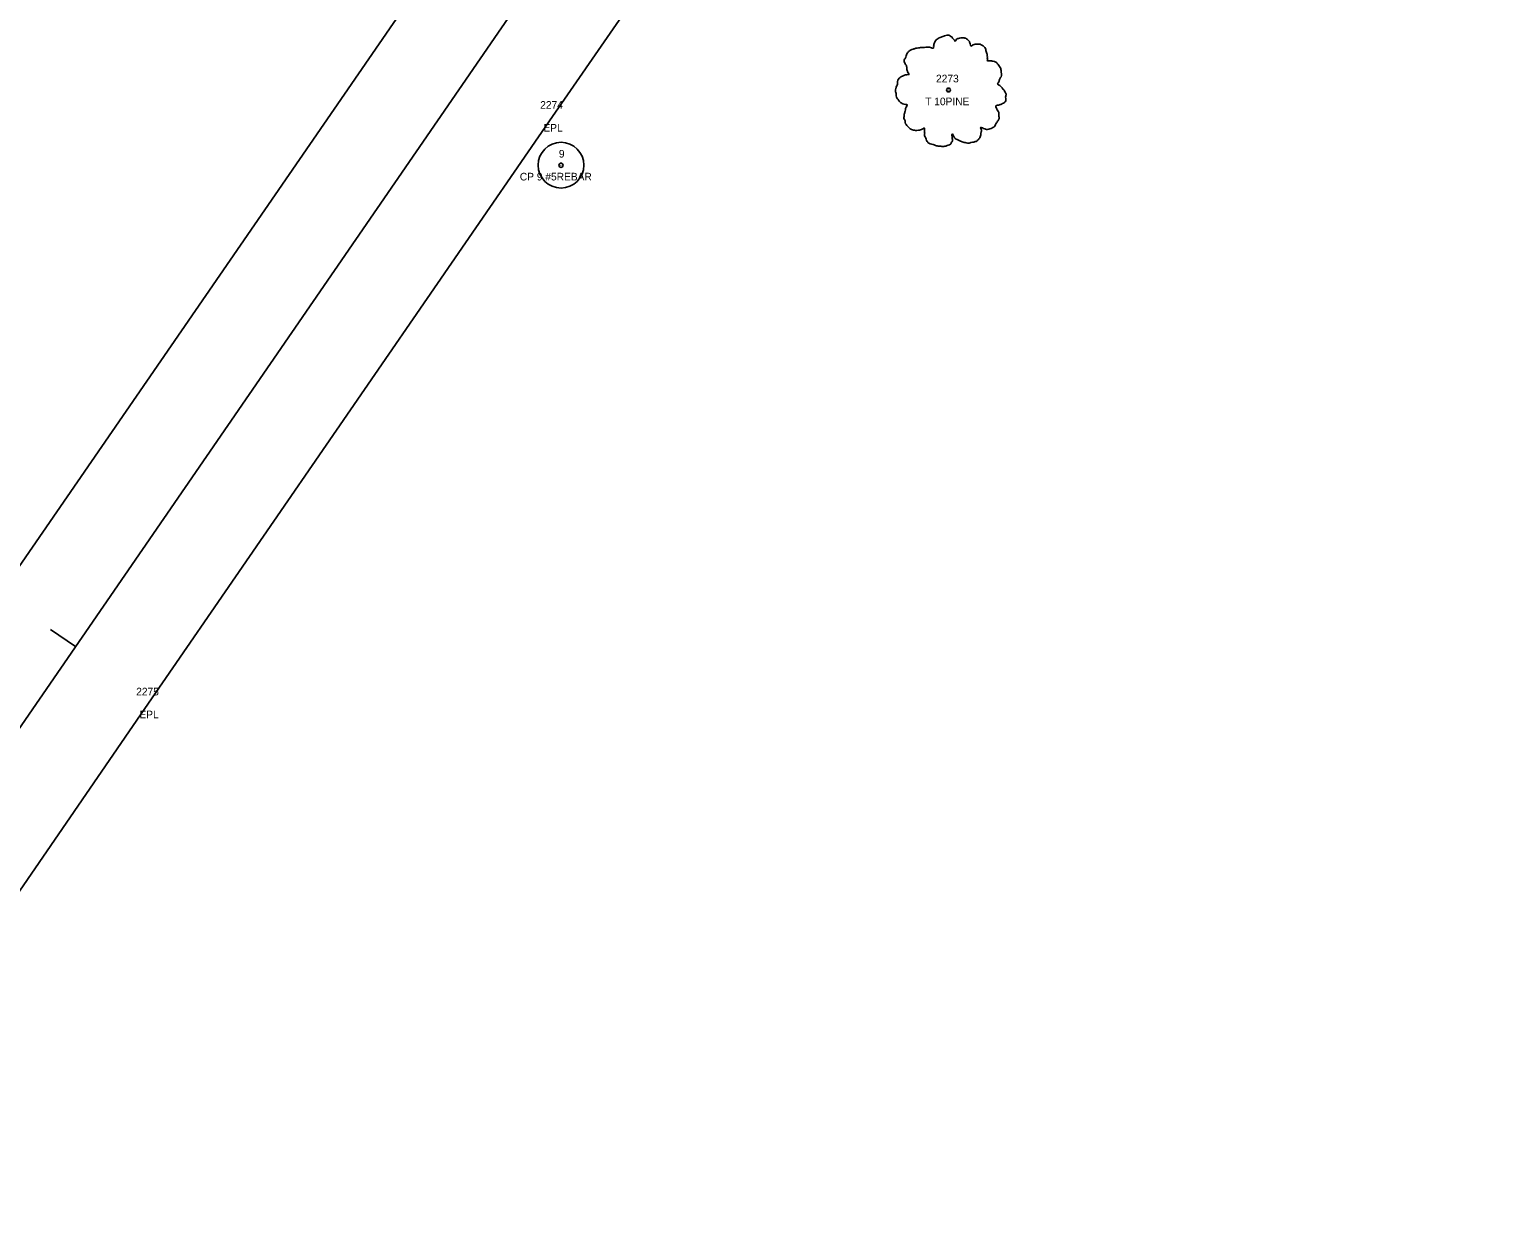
# Model space of a CAD drawing. Extents: x 2266664 to 2272542, y 716533 to 724777.
# Drawn here: x 2271769.3 to 2271962, y 723835.9 to 723993.3 of the extents above; entities that cross this region are included whole.
import ezdxf

# ---------------------------------------------------------------- set-up
doc = ezdxf.new("R2010")
doc.units = 0
for name, color, linetype in [('RD_EX_Road', 7, 'Continuous'), ('RD_EX_Road_txCode', 7, 'Continuous'), ('RD_EX_VEG', 7, 'Continuous'), ('RD_EX_VEG_txCode', 7, 'Continuous'), ('RD_HC_Cl', 7, 'Continuous'), ('RD_HC_Data', 7, 'Continuous'), ('RD_HC_Data_Tic', 7, 'Continuous'), ('RD_HC_txCode', 7, 'Continuous'), ('RD_SMD_Locator', 7, 'Continuous')]:
    doc.layers.add(name, color=color, linetype=linetype)

msp = doc.modelspace()

# ---------------------------------------------------------------- linework, layer by layer
at = {"layer": 'RD_EX_Road'}
for points in [[(2272350.52, 724770.05), (2272301.75, 724698.9), (2272265.2, 724646.02), (2272253.02, 724627.92), (2272200.51, 724550.87), (2272147.54, 724474.34), (2272126.28, 724443.66), (2272107.36, 724416.48), (2272092.2, 724393.69), (2272038.42, 724315.2), (2271991.52, 724247.47), (2271974.41, 724222.16), (2271928.73, 724155.87), (2271879.39, 724084.16), (2271852.9, 724045.63), (2271818.37, 723996.02), (2271765.12, 723918.77), (2271712.35, 723841.58), (2271659.05, 723763.61), (2271604.53, 723684.77), (2271550.65, 723606.61)], [(2272368.97, 724754.13), (2272346.57, 724721.92), (2272321.77, 724685.09), (2272273.25, 724614.42), (2272223.01, 724540.91), (2272206.83, 724517.64), (2272178.6, 724477.03), (2272166.48, 724459.37), (2272137.67, 724416.89), (2272108.53, 724374.93), (2272057.89, 724300.99), (2272036.24, 724269.85), (2272022.13, 724249.17), (2272003.16, 724221.27), (2271948.47, 724142.38), (2271900.7, 724072.99), (2271873.7, 724033.58), (2271837.94, 723981.87), (2271784.96, 723904.95), (2271732.12, 723828.06), (2271678.32, 723749.57), (2271627.92, 723676.62), (2271614.21, 723655.35), (2271570.62, 723593.07)]]:
    msp.add_lwpolyline(points, dxfattribs=at)
at = {"layer": 'RD_EX_VEG'}
for centre, radius in [((2271889.85, 723985.33), 0.25), ((2271889.83, 723985.32), 0.0001)]:
    msp.add_circle(centre, radius, dxfattribs=at)
for points in [[(2271889.98, 723992.5), (2271889.68, 723992.53), (2271889.35, 723992.43), (2271889.1, 723992.33), (2271888.88, 723992.25), (2271888.65, 723992.15), (2271888.35, 723991.98), (2271888.13, 723991.78), (2271888, 723991.53), (2271887.95, 723991.3), (2271887.9, 723991.03), (2271887.9, 723990.85), (2271887.78, 723990.83), (2271887.63, 723990.85), (2271887.38, 723990.93), (2271887.13, 723990.93), (2271886.88, 723990.93), (2271886.53, 723990.9), (2271886.18, 723990.9), (2271885.91, 723990.85), (2271885.58, 723990.8), (2271885.21, 723990.68), (2271884.86, 723990.55), (2271884.56, 723990.3), (2271884.31, 723989.83), (2271884.18, 723989.48), (2271884.03, 723989.23), (2271884.18, 723988.78), (2271884.36, 723988.43), (2271884.38, 723988.23), (2271884.46, 723987.8), (2271884.56, 723987.58), (2271884.68, 723987.38), (2271884.61, 723987.35), (2271884.23, 723987.3), (2271883.93, 723987.2), (2271883.51, 723986.98), (2271883.28, 723986.75), (2271883.18, 723986.43), (2271883.16, 723986.08), (2271883.06, 723985.88), (2271882.98, 723985.61), (2271882.96, 723985.53), (2271882.91, 723985.21), (2271883.01, 723984.76), (2271883.03, 723984.41), (2271883.16, 723984.18), (2271883.31, 723984.01), (2271883.48, 723983.76), (2271883.88, 723983.53), (2271884.21, 723983.43), (2271884.41, 723983.41), (2271884.23, 723982.91), (2271884.18, 723982.56), (2271884.06, 723982.16), (2271884.06, 723982.08), (2271884.01, 723981.61), (2271884.16, 723981.28), (2271884.23, 723980.91), (2271884.41, 723980.68), (2271884.68, 723980.38), (2271885.01, 723980.16), (2271885.51, 723980.03), (2271885.91, 723980.06), (2271886.48, 723980.23), (2271886.73, 723980.31), (2271886.7, 723980.13), (2271886.73, 723979.76), (2271886.73, 723979.33), (2271886.88, 723979.01), (2271886.98, 723978.73), (2271887.13, 723978.48), (2271887.45, 723978.26), (2271887.85, 723978.18), (2271888.28, 723978.03), (2271888.73, 723977.96), (2271889.23, 723977.93), (2271889.83, 723978.08), (2271890.1, 723978.21), (2271890.2, 723978.38), (2271890.4, 723978.76), (2271890.35, 723978.98), (2271890.38, 723979.58), (2271890.48, 723979.41), (2271890.65, 723979.06), (2271891.15, 723978.76), (2271891.55, 723978.58), (2271892.03, 723978.43), (2271892.33, 723978.36), (2271892.8, 723978.43), (2271893.18, 723978.51), (2271893.55, 723978.63), (2271893.85, 723978.91), (2271894.03, 723979.18), (2271894.08, 723979.46), (2271894.15, 723979.83), (2271894.2, 723980.01)], [(2271894.2, 723980.01), (2271894.13, 723980.18), (2271894.08, 723980.43), (2271894.15, 723980.41), (2271894.33, 723980.36), (2271894.6, 723980.23), (2271894.83, 723980.16), (2271895.15, 723980.18), (2271895.43, 723980.28), (2271895.88, 723980.56), (2271896.15, 723981.03), (2271896.43, 723981.43), (2271896.5, 723981.76), (2271896.45, 723981.98), (2271896.43, 723982.48), (2271896.23, 723982.73), (2271896.18, 723982.86), (2271896.08, 723983.26), (2271896.15, 723983.31), (2271896.43, 723983.36), (2271896.8, 723983.48), (2271897.08, 723983.61), (2271897.3, 723983.78), (2271897.38, 723984.01), (2271897.35, 723984.41), (2271897.4, 723984.81), (2271897.33, 723984.96), (2271897.23, 723985.11), (2271897.15, 723985.31), (2271897, 723985.46), (2271896.9, 723985.61), (2271896.8, 723985.7), (2271896.68, 723985.85), (2271896.5, 723985.98), (2271896.35, 723986.03), (2271896.3, 723986.18), (2271896.45, 723986.38), (2271896.5, 723986.48), (2271896.53, 723986.7), (2271896.75, 723987.05), (2271896.8, 723987.45), (2271896.75, 723987.88), (2271896.7, 723988.15), (2271896.55, 723988.43), (2271896.35, 723988.68), (2271896.23, 723988.85), (2271896.05, 723988.98), (2271895.73, 723989.1), (2271895.48, 723989.15), (2271895.13, 723989.15), (2271894.93, 723989.2), (2271894.95, 723989.25), (2271894.95, 723989.4), (2271894.95, 723989.68), (2271894.88, 723990.13), (2271894.73, 723990.63), (2271894.73, 723990.65), (2271894.63, 723990.9), (2271894.4, 723991.1), (2271894.23, 723991.2), (2271894.03, 723991.33), (2271893.78, 723991.35), (2271893.48, 723991.35), (2271893.2, 723991.3), (2271893, 723991.2), (2271892.83, 723991.08), (2271892.75, 723991.23), (2271892.65, 723991.53), (2271892.6, 723991.68), (2271892.45, 723991.85), (2271892.23, 723992.05), (2271891.78, 723992.18), (2271891.15, 723992.1), (2271890.85, 723991.9), (2271890.7, 723991.73), (2271890.65, 723991.85), (2271890.45, 723992.05), (2271890.35, 723992.23), (2271890.18, 723992.35), (2271890.03, 723992.45), (2271889.93, 723992.5)]]:
    msp.add_spline(points, degree=3, dxfattribs=at)
at = {"layer": 'RD_HC_Cl'}
msp.add_line((2267342.91, 717471.2), (2272360.46, 724762.59), dxfattribs=at)
at = {"layer": 'RD_HC_Data'}
for radius in [3, 0.282]:
    msp.add_circle((2271839.04, 723975.47), radius, dxfattribs=at)
at = {"layer": 'RD_HC_Data_Tic'}
msp.add_line((2271775.36, 723912.35), (2271772.07, 723914.61), dxfattribs=at)
at = {"layer": 'RD_SMD_Locator'}
for centre in [(2271837.94, 723981.87), (2271839.04, 723975.47), (2271784.96, 723904.95)]:
    msp.add_circle(centre, 0.001, dxfattribs=at)

# ---------------------------------------------------------------- texts
at = {"layer": 'RD_EX_Road_txCode'}
for s, p in [('2274', (2271836.31, 723982.87)), ('EPL', (2271836.73, 723979.87)), ('2275', (2271783.33, 723905.95)), ('EPL', (2271783.75, 723902.95))]:
    msp.add_text(s, height=1, dxfattribs=at).set_placement(p)
at = {"layer": 'RD_EX_VEG_txCode'}
for s, p in [('2273', (2271888.22, 723986.33)), ('T 10PINE', (2271886.8, 723983.33))]:
    msp.add_text(s, height=1, dxfattribs=at).set_placement(p)
at = {"layer": 'RD_HC_txCode'}
for s, p in [('9', (2271838.76, 723976.47)), ('CP 9 #5REBAR', (2271833.64, 723973.47))]:
    msp.add_text(s, height=1, dxfattribs=at).set_placement(p)

doc.saveas('drawing.dxf')
